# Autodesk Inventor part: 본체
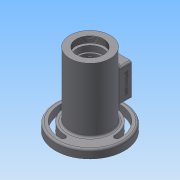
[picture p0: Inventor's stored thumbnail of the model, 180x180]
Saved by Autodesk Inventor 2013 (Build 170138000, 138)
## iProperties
Created: 2017-05
Part Number: 본체
Material: Generic
Document SubType Name: Modeling
Designer: Administrator
Density: 1 g/cm^3
Author: Administrator
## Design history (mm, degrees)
sketch "스케치1"
  geometry: C1 r 31 at (0, 0); 1 further point
  constraints: 1 centre point, 1 coincident
  dimensions: "d0" = 62 diameter of C1
extrude "돌출1" new body sketch "스케치1" stored distance "d2" = 115; taper "d3" = 0 deg
sketch "스케치2"
  geometry: L1 (31, 57.5)-(-31, 57.5) reference; L2 (-31, -57.5)-(31, -57.5) reference; L3 (0, 57.5)-(0, -57.5); L4 (21, 57.5)-(21, 48.5); L5 (21, 48.5)-(24, 48.5); L6 (24, 48.5)-(24, 45.5); L7 (24, 45.5)-(20, 45.5); L8 (20, 45.5)-(20, 36.5); L9 (20, 36.5)-(17.5, 36.5); L10 (17.5, 36.5)-(17.5, 33.25); L11 (17.5, 33.25)-(18.5, 33.25); L12 (18.5, 33.25)-(18.5, 31.5); L13 (18.5, 31.5)-(17.5, 31.5); L14 (17.5, 31.5)-(17.5, 20.5); L15 (17.5, 20.5)-(26, 20.5); L16 (26, 20.5)-(26, -17.5); L17 (12.5, -36.2)-(12.5, -43.5); L18 (16, -43.5)-(22, -57.5); L19 (12.5, -36.2)-(10, -36.2); L20 (10, -36.2)-(10, -33.5); L21 (10, -33.5)-(16.5, -33.5); L22 (16.5, -33.5)-(16.5, -28.5); L23 (16.5, -28.5)-(17.5, -28.5); L24 (17.5, -28.5)-(17.5, -17.5); L25 (17.5, -17.5)-(26, -17.5); L26 (12.5, -39.269)-(12.5, -39.269); L27 (12.5, -43.5)-(16, -43.5); 1 further point
  constraints: 50 end point, 11 perpendicular, 10 parallel, 3 point on line, 2 midpoint, 1 collinear, 1 vertical alignment
  dimensions: "d4" = 42 diameter of L4 L3; "d6" = 48 diameter of L6 L3; "d7" = 40 diameter of L8 L3; "d8" = 44 diameter of L18.end L3; "d10" = 14 vertical distance of L18.start L18.end; "d12" = 20 diameter of L20 L3; "d13" = 33 diameter of L22 L3; "d14" = 35 diameter of L24 L3; "d15" = 52 diameter of L16 L3; "d16" = 35 diameter of L10 L3; "d17" = 37 diameter of L12 L3; "d18" = 12 distance between parallel lines of L7 L1; "d19" = 3 distance of L5.end L6.end; "d20" = 21 distance between parallel lines of L9 L1; "d21" = 26 distance from line of L12.end L1; "d22" = 38 distance of L15.end L16.end; "d23" = 11 distance of L13.end L14.end; "d27" = 32 diameter of L18.start L3; "d28" = 2.7 distance of L19.end L20.end; "d29" = 25 diameter of L17 L3; "d30" = 7.3 distance of L17.start L17.end; "d31" = 1.75 distance of L11.end L12.end
revolve "회전1" sketch "스케치2" stored, may be unused: angle "d32" = 90 deg
node "작업 평면1"
sketch "스케치3"
  geometry: C1 r 53 at (0, 0); C2 r 31 at (0, 0) reference; C3 r 31 at (0, 0); 1 further point
  constraints: 2 centre point, 2 coincident, 1 concentric
  dimensions: "d34" = 106 diameter of C1
extrude "돌출2" join sketch "스케치3" distance "d36" = 13; taper "d37" = 0 deg
sketch "스케치4"
  geometry: C1 r 31 at (0, 0) reference; A1 r 41.5 centre (0, 0) between (-41.5, 0) and (41.5, 0); A2 r 4 centre (-41.5, 0) between (-45.5, 0) and (-37.5, 0); A3 r 4 centre (41.5, 0) between (45.5, 0) and (37.5, 0); A4 r 4 centre (0, 41.5) between (0, 37.5) and (0, 45.5); A5 r 4 centre (0, -41.5) between (0, -37.5) and (0, -45.5); A6 r 37.5 centre (0, 0) between (0, -37.5) and (37.5, 0); A7 r 37.5 centre (0, 0) between (0, 37.5) and (-37.5, 0); A8 r 45.5 centre (0, 0) between (0, -45.5) and (45.5, 0); A9 r 45.5 centre (0, 0) between (0, 45.5) and (-45.5, 0)
  constraints: 20 point on circle, 9 centre point, 5 equal radius, 2 horizontal alignment, 2 vertical alignment
  dimensions: "d38" = 83 diameter of A1; "d42" = 45.5 radius of A9; "d43" = 37.5 radius of A7; "d44" = 8 diameter of A2
extrude "돌출3" cut sketch "스케치4" distance "d45" = 13; taper "d46" = 0 deg
node "작업 평면2"
sketch "스케치5"
  geometry: L1 (20, 26.5)-(20, -23.5); L2 (20, -23.5)-(-20, -23.5); L3 (-20, -23.5)-(-20, 26.5); L4 (-20, 26.5)-(20, 26.5); L5 (20, 26.5)-(-20, -23.5); L6 (20, -23.5)-(-20, 26.5); L7 (31, 57.5)-(-31, 57.5) reference; L8 (31, -41.5)-(31, 57.5) reference; 2 further points
  constraints: 12 end point, 2 midpoint, 2 parallel, 1 perpendicular, 1 vertical
  dimensions: "d48" = 56 distance from line of point (0, 1.5) L7; "d49" = 31 distance from line of point (0, 1.5) L8; "d50" = 50 distance of L2.end L3.end; "d51" = 40 distance of L3.end L1.start
extrude "돌출4" join sketch "스케치5" stored distance "d52" = 13; taper "d53" = 0 deg
sketch "스케치6"
  geometry: L1 (-20, -26.5)-(-20, 23.5) reference; L2 (20, -26.5)-(-20, -26.5) reference; L3 (20, 23.5)-(20, -26.5) reference; L4 (-20, 23.5)-(20, 23.5) reference; L5 (11, 14.5)-(11, -17.5); L6 (11, -17.5)-(-11, -17.5); L7 (-11, -17.5)-(-11, 14.5); L8 (-11, 14.5)-(11, 14.5); 1 further point
  constraints: 8 end point, 3 other
  dimensions: "d54" = 32 distance of L5.start L5.end
extrude "돌출5" cut sketch "스케치6" stored distance "d56" = 13; taper "d57" = 0 deg
sketch "스케치8"
  geometry: L1 (50, 0)-(0, 0) reference; L2 (-31, -13)-(-31, -75) reference; 2 further points
  constraints: 1 other
  dimensions: "d70" = 56 distance from line of point (25, -8) L2; "d71" = 8 distance from line of point (25, -8) L1
feature "엠보싱1" sketch "스케치8" dims "d2" = 115, "d3" = 0, "d4" = 42, "d6" = 48, "d7" = 40, "d8" = 44, "d10" = 14, "d12" = 20, "d13" = 33, "d14" = 35, "d15" = 52, "d16" = 35, "d17" = 37, "d18" = 12, "d19" = 3, "d20" = 21, "d21" = 26, "d22" = 38, "d23" = 11, "d27" = 32, "d28" = 2.7, "d29" = 25, "d30" = 7.3, "d31" = 1.75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
feature "스레드1" dims "d74" = 10, "d75" = 0
fillet "모깎기1" dims "d76" = 3
fillet "모깎기2" dims "d77" = 3
fillet "모깎기3" dims "d78" = 3
fillet "모깎기4" dims "d79" = 3
fillet "모깎기5" dims "d80" = 3
fillet "모깎기6" dims "d81" = 3
chamfer "모따기2" distance "d85" = 1; stored, may be unused: second distance "d86" = 2, angle "d87" = 45 deg
fillet "모깎기7" dims "d90" = 3
fillet "모깎기8" dims "d106" = 3
fillet "모깎기9" dims "d122" = 0.3
sketch "스케치13"
  geometry: 5 further points
  constraints: 2 horizontal alignment, 2 vertical alignment
  dimensions: "d126" = 31 distance of point (15.5, 20.5) point (-15.5, 20.5); "d128" = 41 distance of point (-15.5, -20.5) point (-15.5, 20.5); "d129" = 15.5 horizontal distance of point (0, 0) point (-15.5, 20.5); "d130" = 20.5 vertical distance of point (0, 0) point (-15.5, 20.5)
hole "구멍4" sketch "스케치13" at (-15.5, -20.5), (-15.5, 20.5), (15.5, 20.5), (15.5, -20.5) diameter "d131" = 2.459; stored, may be unused: countersink angle "d135" = 90 deg, drill point angle "d137" = 118 deg; dims "d132" = 6, "d133" = 4, "d134" = 2, "d136" = 8
node "솔리드1"
other parameters: "d33" = -3, "d40" = 91, "d41" = 75, "d47" = 44
